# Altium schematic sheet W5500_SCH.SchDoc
size A4
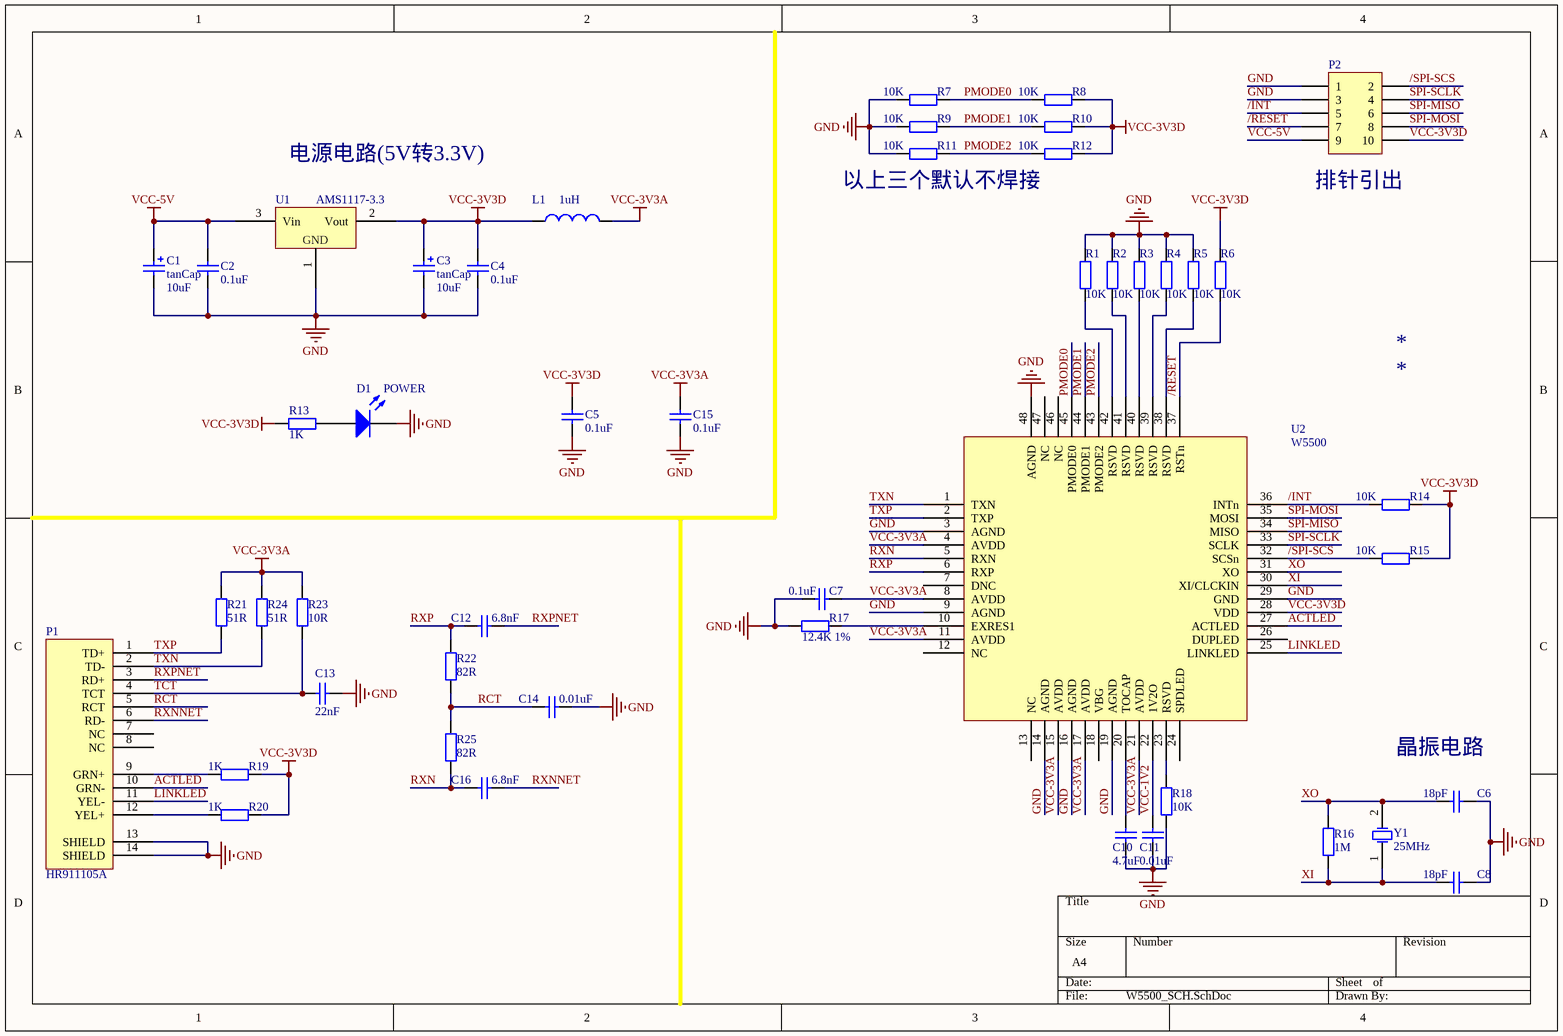
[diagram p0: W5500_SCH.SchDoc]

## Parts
C1  tanCap  value 10uF  [C1206]
C2  value 0.1uF  [C0805]  (hidden comment: Cap)
C3  tanCap  value 10uF  [C1206]
C4  value 0.1uF  [C0805]  (hidden comment: Cap)
C5  value 0.1uF  [C0805]  (hidden comment: Cap)
C6  value 18pF  [C0805]  (hidden comment: Cap)
C7  value 0.1uF  [C0805]  (hidden comment: Cap)
C8  value 18pF  [C0805]  (hidden comment: Cap)
C10  value 4.7uF  [C0805]  (hidden comment: Cap)
C11  value 0.01uF  [C0805]  (hidden comment: Cap)
C12  value 6.8nF  [C0805]  (hidden comment: Cap)
C13  value 22nF  [C0805]  (hidden comment: Cap)
C14  value 0.01uF  [C0805]  (hidden comment: Cap)
C15  value 0.1uF  [C0805]  (hidden comment: Cap)
C16  value 6.8nF  [C0805]  (hidden comment: Cap)
D1  POWER  [C0805]
L1  value 1uH  [C0805]  (hidden comment: Inductor)
P1  HR911105A  [HR911105A]
P2  排针引出  [HDR2X5]
R1  value 10K  [C0805]  (hidden comment: Res2)
R2  value 10K  [C0805]  (hidden comment: Res2)
R3  value 10K  [C0805]  (hidden comment: Res2)
R4  value 10K  [C0805]  (hidden comment: Res2)
R5  value 10K  [C0805]  (hidden comment: Res2)
R6  value 10K  [C0805]  (hidden comment: Res2)
R7  value 10K  [C0805]  (hidden comment: Res2)
R8  value 10K  [C0805]  (hidden comment: Res2)
R9  value 10K  [C0805]  (hidden comment: Res2)
R10  value 10K  [C0805]  (hidden comment: Res2)
R11  value 10K  [C0805]  (hidden comment: Res2)
R12  value 10K  [C0805]  (hidden comment: Res2)
R13  value 1K  [C0805]  (hidden comment: Res2)
R14  value 10K  [C0805]  (hidden comment: Res2)
R15  value 10K  [C0805]  (hidden comment: Res2)
R16  value 1M  [C0805]  (hidden comment: Res2)
R17  value 12.4K 1%  [C0805]  (hidden comment: Res2)
R18  value 10K  [C0805]  (hidden comment: Res2)
R19  value 1K  [C0805]  (hidden comment: Res2)
R20  value 1K  [C0805]  (hidden comment: Res2)
R21  value 51R  [C0805]  (hidden comment: Res2)
R22  value 82R  [C0805]  (hidden comment: Res2)
R23  value 10R  [C0805]  (hidden comment: Res2)
R24  value 51R  [C0805]  (hidden comment: Res2)
R25  value 82R  [C0805]  (hidden comment: Res2)
U1  AMS1117-3.3  [SOT223_M]
U2  W5500  [LQFP48]
Y1  25MHz  [XTAL-HC49]

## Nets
GND: C1.2 C2.2 C3.2 C4.2 C5.2 C6.1 C7.2 C8.1 C10.2 C11.2 C13.2 C14.1 C15.1 D1.2(K) P1.13(SHIELD) P1.14(SHIELD) P2.1 P2.3 R1.2 R2.2 R3.2 R4.2 R5.2 R7.1 R9.1 R11.1 R17.1 R18.1 U1.1(GND) U2.3(AGND) U2.9(AGND) U2.14(AGND) U2.16(AGND) U2.19(AGND) U2.29(GND) U2.48(AGND)
VCC-3V3A: C7.1 C15.2 L1.2 R21.1 R23.1 R24.1 U2.4(AVDD) U2.8(AVDD) U2.11(AVDD) U2.15(AVDD) U2.17(AVDD) U2.21(AVDD)
VCC-3V3D: C3.1 C4.1 C5.1 L1.1 P2.10 R6.2 R8.2 R10.2 R12.2 R13.2 R14.2 R15.2 R19.1 R20.1 U1.2(Vout) U2.28(VDD)
VCC-5V: C1.1 C2.1 P2.9 U1.3(Vin)
/INT: P2.5 R14.1 U2.36(INTn)
/RESET: P2.7 R6.1 U2.37(RSTn)
/SPI-SCS: P2.2 R15.1 U2.32(SCSn)
ACTLED: P1.10(GRN-) U2.27(ACTLED)
LINKLED: P1.11(YEL-) U2.25(LINKLED)
PMODE0: R7.2 R8.1 U2.45(PMODE0)
PMODE1: R9.2 R10.1 U2.44(PMODE1)
PMODE2: R11.2 R12.1 U2.43(PMODE2)
RCT: C14.2 P1.5(RCT) R22.1 R25.2
RXN: C16.2 R25.1 U2.5(RXN)
RXNNET: C16.1 P1.6(RD-)
RXP: C12.2 R22.2 U2.6(RXP)
RXPNET: C12.1 P1.3(RD+)
SPI-MISO: P2.6 U2.34(MISO)
SPI-MOSI: P2.8 U2.35(MOSI)
SPI-SCLK: P2.4 U2.33(SCLK)
TCT: C13.1 P1.4(TCT) R23.2
TXN: P1.2(TD-) R24.2 U2.1(TXN)
TXP: P1.1(TD+) R21.2 U2.2(TXP)
VCC-1V2: C11.1 U2.22(1V2O)
XI: C8.2 R16.1 U2.30(XI/CLCKIN) Y1.1(OSC1)
XO: C6.2 R16.2 U2.31(XO) Y1.2(OSC2)
NetC10_1: C10.1 U2.20(TOCAP)
NetD1_1: D1.1(A) R13.1
NetP1_9: P1.9(GRN+) R19.2
NetP1_12: P1.12(YEL+) R20.2
NetR1_1: R1.1 U2.42(RSVD)
NetR2_1: R2.1 U2.41(RSVD)
NetR3_1: R3.1 U2.40(RSVD)
NetR4_1: R4.1 U2.39(RSVD)
NetR5_1: R5.1 U2.38(RSVD)
NetR17_2: R17.2 U2.10(EXRES1)
NetR18_2: R18.2 U2.23(RSVD)

Not connected (* = marked no-connect by the designer): P1 7(NC) 8(NC); U2 7(DNC) 12(NC) 13(NC) 18(VBG) 24(SPDLED) 26(DUPLED) 46(NC) 47(NC)

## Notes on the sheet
- 电源电路(5V转3.3V)
- (near R11) 以上三个默认不焊接
- (near C6) 晶振电路

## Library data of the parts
C1 C3 = Cap Pol2: Polarized Capacitor (Axial)
C2 C4-C8 C10-C16 = Cap: Capacitor
D1 = LED0: Typical INFRARED GaAs LED
L1 = Inductor: Code_IEC: 1005
P1 = HR911105A: RJ45插座
P2 = Header 5X2: Header, 5-Pin, Dual row
R1-R25 = Res2: Resistor
U1 = AMS1117: AMS1117-
U2 = W5500: W5500以太网芯片
Y1 = XTAL: Crystal Oscillator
